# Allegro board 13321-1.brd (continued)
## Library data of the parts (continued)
PC4715 PC4716 PC4724-PC4728 PC4734 PC4736 PC4737 PC4743 = C805H58: tolerance: 78.22610.51L
PC4805 PC4810-PC4813 PC4901 PC4903-PC4905 = C805H58: tolerance: 78.22610.L2L
PC4806 = C603H36: tolerance: 78.10422.L0L
PC4907 = C402H22: tolerance: 78.10324.L0L
PD4201 = D5436AKH98: tolerance: 83.22R03.03G
PD4204 = SOT-23-10H44: tolerance: 83.0024V.0A1
PD4302 = SOD123FLAKH40: tolerance: 83.SMF18.0AH
PD4401 PD4405 PD4406 = SOD323AKH40: tolerance: 83.1R504.B8F
PD4402 = SMPC4665-3P-UH48: tolerance: 83.8R010.A87
PD4403 = SOD323AKH42: tolerance: 83.04148.D1H
PG4401-PG4408 PG4532 PG4535 PG4707 PG4708 PG4801 = GAP-CLOSE-PWR-3: tolerance: ZZ.CLOSE.001
PG4901-PG4909 PG4917 PG4918 PG5101 = GAP-CLOSE-PWR: tolerance: ZZ.CON2d.XXX
PL4401 = L11510030H158: tolerance: 68.2R210.20C
PL4501 = L736630H119: tolerance: 68.3R310.20A
PL4503 = L7066-1830-UH119: tolerance: 68.4R71A.20H
PL4701 = L109100-2430-UH158: tolerance: 068.R2210.2011
PL4801 PL4901 = L4947-1015H119: tolerance: 68.R6810.20E
PQ4201 Q1201 = SOT23DGS2D4H44: tolerance: 84.00301.A31
PQ4202 Q2603 Q5401 = SOT23CBE2D6H46: tolerance: 84.03904.P11
PQ4401 PQ4406 Q1202 Q1901 Q2401 Q2403 Q2505 Q2602 Q2901 Q5403 Q5404 Q6205 = SOT23DGS2D4H44: tolerance: 84.2N702.J31
PQ4405 PQ4407 PQ4411 PQ4413 Q1701 Q1801 Q2601 Q3601 Q5402 Q6204 Q6701 U2901 = SOT-363H44: tolerance: 84.2N702.A3F
PQ4408 Q2404 = SOT23CBE2D4H44: tolerance: 84.T3906.A11
PR4202 PR4527 R3024 = R402H16: tolerance: 64.15025.6DL
PR4203 PR4909 R405 R706 R710 R1701 R1717 R1724 R1726 R1902 R1905 R2001 R2004 R2017 R2021-R2025 R2414 R2415 R2418 R2436 R2439 R2443 R2446 R2448 R2451 R2452 R2454 R2916 R2919 R2920 R5412 R5420 R6203 R6609-R6620 R6623 R6626 = R402H16: tolerance: 63.10334.1DL
PR4204 = R402H16: tolerance: 63.22234.1DL
PR4205 PR4206 R5205 = R402H16: tolerance: 63.33034.1DL
PR4207 = R603H22: tolerance: 63.24434.15L
PR4208 = R603H22: tolerance: 63.47333.15L
PR4209 PR4410 PR4412 PR4416 PR4429 PR4435 PR4437 PR4449 PR4470 PR4471 PR4534 R1715 R1727 R2007 R2013 R2412 R2413 R2421 R2442 R2445 R2447 R2450 R2455 R2711 R2722 R2905 R2918 R3503 R3607 R5413 R6208 R6401 R6602 R6701 = R402H16: tolerance: 63.10434.1DL
PR4401 = R402H16: tolerance: 64.18235.6DL
PR4402 PR4420 PR4607 PR4806 = R402H16: tolerance: 64.75025.6DL
PR4403 = R805H24: tolerance: 63.10031.16L
PR4404 PR4440 = R402H16: tolerance: 63.12434.1DL
PR4405 PR4424 PR4431 PR4441 PR4453 PR4460 PR4461 R707 R713 R1725 R2406 R2407 = R402H16: tolerance: 64.10035.6DL
PR4406 PR4417 PR4430 PR4434 PR4438 PR4455 PR4458 PR4462 PR4466 PR4467 PR4469 PR4504 PR4506 PR4515 PR4532 PR4615 PR4625 PR4702 PR4802 PR4804 PR4807 PR4902 PR4905-PR4907 PR4914 PR5101 R404 R1201 R1202 R1205 R1501 R1706 R1707 R1709 R1710 R1713 R1718 R1729 R1810 R1904 R2002 R2008-R2010 R2015 R2016 R2019 R2020 R2028 R2101 R2103 R2105 R2112 R2117 R2118 R2401 R2416 R2417 R2426-R2428 R2430 R2435 R2437 R2440 R2441 R2444 R2453 R2457 R2601 R2611 R2612 R2701 R2705 R2708 R2714 R3413-R3416 R3501 R3504 R3505 R3507 R3609-R3611 R3802 R4301 R5201 R5202 R5421 R5422 R5601 R6202 R6216 R6622 R6625 R6628 R6629 = 0R0402-PAD-1: tolerance: ZZ.00PAD.M11
PR4407 = R402H16: tolerance: 64.6R805.6DL
PR4408 = R603H22: tolerance: 64.20R05.55L
PR4409 = R402H16: tolerance: 64.10015.6DL
PR4411 R709 R712 = R402H16: tolerance: 64.47025.6DL
PR4413 PR4415 PR4419 PR4421 PR4448 PR4452 PR4456 PR4457 PR4463 PR4464 PR4501 PR4525 PR4530 PR4535 PR4626 PR4917 PR4918 PR4925 PR4926 R1704 R1705 R1708 R1728 R2005 R2026 R2027 R2123 R2424 R2434 R2438 R2602 R2710 R2712 R2716 R2923 R3704 R3710 R5224 R5418 R6212 R6213 R6603 R6608 R6621 R6624 R6627 R6705-R6709 = R402H16: tolerance: 63.R0034.1DL
PR4414 PR4432 = R402H16: tolerance: 63.33234.1DL
PR4418 = R1206H28: tolerance: 63.33232.11L
PR4422 = R402H16: tolerance: 63.18534.L0L
PR4423 PR4450 PR4523 PR4619 R2405 = R402H16: tolerance: 64.10025.6DL
PR4425 PR4801 R2917 R5423 R6205 R6211 = R603H22: tolerance: 63.00000.00L
PR4426 = R3720H40: tolerance: 64.R0105.7FL
PR4427 PR4529 PR4533 PR4701 = R805H24: tolerance: 64.2R205.16L
PR4428 PR4468 PR4601 PR4903 R5411 = R402H16: tolerance: 64.15035.6DL
PR4433 R1802 R1901 = R402H16: tolerance: 63.10534.1DL
PR4436 = R402H16: tolerance: 64.22035.6DL
PR4439 = R402H16: tolerance: 64.40215.6DL
PR4442 = R402H16: tolerance: 64.41235.6DL
PR4443 = R2512H32: tolerance: 64.R0105.97L
PR4444 = R402H16: tolerance: 64.28735.6DL
PR4445 = R402H16: tolerance: 64.33025.6DL
PR4446 R2433 R2707 R3506 R6204 = R402H16: tolerance: 64.20025.6DL
PR4447 = R402H16: tolerance: 64.18035.6DL
PR4451 = R402H16: tolerance: 64.68035.6DL
PR4454 R2609 R2908 R2910 = R402H14: tolerance: 64.10R05.6DL
PR4465 = R402H16: tolerance: 64.31635.6DL
PR4502 = R402H16: tolerance: 63.20134.1DL
PR4512 = R402H16: tolerance: 64.66515.6DL
PR4517 = R402H16: tolerance: 64.34825.6DL
PR4524 PR4528 = R603H22: tolerance: 63.1R534.15L
PR4526 = R402H16: tolerance: 64.97615.6DL
PR4531 = R402H16: tolerance: 64.49925.6DL
PR4602 = NTC-402H22-U: tolerance: 69.60037.031
PR4603 PR4611 R703 = R402H16: tolerance: 64.75R05.6DL
PR4604 = R402H16: tolerance: 64.49935.6DL
PR4605 = R402H16: tolerance: 64.71525.6DL
PR4608 PR4612 = R402H16: tolerance: 64.39025.6DL
PR4609 = R402H16: tolerance: 64.56025.6DL
PR4610 = R402H16: tolerance: 64.39235.6DL
PR4613 PR4618 PR4624 = R603H22: tolerance: 63.10033.15L
PR4614 R2607 = R402H16: tolerance: 64.20015.6DL
PR4616 PR4617 R1801 R1807-R1809 R1811 R1812 R1908 R2718 R2719 R5401-R5408 R6601 R6604 = 0R0402-PAD-1: tolerance: ZZ.00PAD.M11; signal model: R402H16_0R2J-2-GP
PR4620 = R402H16: tolerance: 64.34015.6DL
PR4621 PR4623 R704 = R402H16: tolerance: 64.13005.6DL
PR4622 = R402H16: tolerance: 64.54R95.6DL
PR4627 = R402H16: tolerance: 64.47515.6DL
PR4703 PR4901 = R603H24: tolerance: 64.2R205.L0L
PR4704 = R402H16: tolerance: 64.23215.6DL
PR4705 = R402H16: tolerance: 64.16225.6DL
PR4706 = R402H16: tolerance: 64.29415.6DL
PR4707 = NTC-402H22-U: tolerance: 69.60037.011
PR4803 = R402H16: tolerance: 63.10534.L1L
PR4805 = R402H16: tolerance: 64.10035.L3L
PR4904 = R402H16: tolerance: 64.12035.6DL
PR4910 R604 R605 R1702 R1703 R1909 R1919 R2006 R2011 R2012 R2014 R2018 R2432 R2449 R2717 R2921 R2922 R3601 R3603 R6201 = R402H16: tolerance: 63.10234.1DL
PT4501 PT4502 = CT3528H79: tolerance: 77.C2271.45L
PT4702 = CT7343H119: tolerance: 77.23361.061
PU4201 PU4403 PU4405 = PPAK-8P-2H45: tolerance: 84.07121.037
PU4401 = QFN28-G2D7H32: tolerance: 074.24770.0003
PU4402 = TSOIC8H48: tolerance: 74.00393.C2G
PU4404 = SC70-6H44: tolerance: 74.00199.07P
PU4406 = PPAK-8P-G5324H44-COLAY: tolerance: ZZ.00215.037
PU4501 PU4502 = SON5Z3025H18: tolerance: 84.87381.03G
PU4503 = QFN20-G1D75H32: tolerance: 74.51225.073
PU4601 = QFN32J4-G2D9-U1H40: tolerance: 74.51624.073
PU4701 = DFN8J4535-G4122-U1H40: tolerance: 74.97374.043
PU4801 = QFN10M3-G4P-UH34: tolerance: 74.08208.K73
PU4901 = QFN10M3-G4P-UH34: tolerance: 74.08206.C73
PU4902 = MSOP10-G2D5H44: tolerance: 74.05338.079
PU5101 = SOT-23-5H58: tolerance: 74.70215.03F
Q2402 Q6203 = SOT23DGS2D4H48: tolerance: 84.02130.031
Q6201 = SOT23CBE2D4H44: tolerance: 84.00144.N11
Q6202 = SOT23DGS2D8H56: tolerance: 84.P8503.031
R401 = R402H16: tolerance: 63.62034.1DL
R402 R406 R1916-R1918 R1920 = R402H16: tolerance: 63.51034.1DL
R403 = R402H16: tolerance: 63.56034.1DL
R407 = R402H16: tolerance: 64.20005.6DL
R408 = R402H16: tolerance: 64.12105.6DL
R409 R702 R901 = R402H14: tolerance: 64.10005.6DL
R410 = R402H16: tolerance: 63.47134.1DL
R601 R602 R606 R2003 = R402H16: tolerance: 64.49R95.6DL
R603 R1714 = R402H16: tolerance: 64.82015.6DL
R701 R2429 = R402H16: tolerance: 63.43034.1DL
R705 R5414-R5417 = R402H16: tolerance: 63.15134.1DL
R801 R3707 R3711 = R402H16: tolerance: 64.24R95.6DL
R1204 = R402H16: tolerance: 63.20534.1DL
R1206 R1207 = R402H16: tolerance: 64.66R55.6DL
R1208 = R402H16: tolerance: 63.22434.1DL
R1601 R1803 R1906 = R402H16: tolerance: 64.30015.6DL
R1602 = R402H16: tolerance: 64.22R65.6DL
R1720 R1721 R1903 R1913 R2425 R2431 = R402H16: tolerance: 63.33434.1DL
R1804 R2720 = R402H16: tolerance: 63.R0034.1DL; signal model: R402H16_0R2J-2-GP
R1805 R1806 R1907 R1912 R2419 R2420 R2422 R2423 = R402H16: tolerance: 63.33034.1DL; signal model: R402H16_33R2J-2-GP
R1911 = R402H16: tolerance: 63.33034.1DL; signal model: R402H16_0R2J-2-GP
R1915 R2504 = R402H16: tolerance: 63.10634.1DL
R2110 = R402H16: tolerance: 64.5R105.6DL
R2114 R3801 = R805H24: tolerance: 63.R0031.16L
R2403 = R603H22: tolerance: 64.2R205.55L
R2404 = R402H16: tolerance: 64.64925.6DL
R2408 R2409 R5419 = 0R0402-PAD: tolerance: ZZ.R0402.001
R2501 R2912 R2913 = R402H16: tolerance: 63.47234.1DL
R2603 R2604 = R402H16: tolerance: 64.75015.6DL
R2608 = R402H16: tolerance: 64.24325.6DL
R2610 = NTC-603H38: tolerance: 69.60035.041
R2709 R3602 R5410 = R402H16: tolerance: 64.20035.6DL
R2914 R5233 R6702 = R603H22: tolerance: 63.R0033.15L
R2915 = R402H16: tolerance: 63.47434.1DL
R3508 = R402H16: tolerance: 64.22125.6DL
R3701 R3703 R3706 R3709 = R402H16: tolerance: 64.18015.6DL
R3702 R3708 = R402H16: tolerance: 64.2R005.6DL
R5203 R5204 = R402H14: tolerance: 63.10134.1DL
R6210 = R603H22: tolerance: 63.10133.15L
R6605 = R402H16: tolerance: 64.15015.6DL
R6606 = R402H16: tolerance: 63.20334.1DL
RN401 = ARES8-CN24H22: tolerance: 66.51036.A8L
RN1501 RN1811 RN2008 RN2602 RN2901 RN5401 RN6204 RN6601 = ARES2H16: tolerance: 66.22236.04L
RN1505 RN1506 RN1601 RN1809 RN1902 RN2002 RN2011 RN2012 = ARES8-CN24-MUH20: tolerance: 66.10336.08L
RN1701 RN1703 RN1801 RN1803 RN1804 RN1810 RN2006 RN2007 RN6201 = ARES2H18: tolerance: 66.10336.04L
RN1702 = SMD-ARES4H20: tolerance: 66.R0036.04L
RN1802 = SMD-ARES4H18: tolerance: 66.10236.04L
RN1806 = ARES8-CN24H22: tolerance: 66.R0036.A8L; signal model: ARES8-CN24H22_SRN0J-7-GP-U
RN1807 = ARES8-CN24-UH20: tolerance: 66.22236.A8L
RN1901 = SMD-ARES4H20: tolerance: 66.20336.04L
RN2401 = SMD-ARES4H18: tolerance: 66.47236.04L
RN2601 RN2701 RN6604 = 0R4P2R-PAD: tolerance: ZZ.0R04P.ZZZ
RN4301 RN5201 = ARES8-CN24H20: tolerance: 66.10136.A8L
RN5203 = ARES8-CN24H20: tolerance: 66.10436.A8L
RN5402 RN5403 = ARES8-CN24H20: tolerance: 66.47136.08L
RN6202 = SMD-ARES4H18: tolerance: 66.33036.04L
SPI25 = SOIC8-1H86: tolerance: 72.25647.00A
SPR1 SPR2 = SPR7732H229: tolerance: 34.4T025.001
TC1201 = CT7343H79: tolerance: 79.33719.20L
THM261 = MSOP8-1H44: tolerance: 74.07718.0B9
TP1 = 50505-0084N-002: tolerance: 20.K0667.008
TP402 TP501 TP601-TP608 TP619 TP620 TP701-TP705 TP801 TP1501 TP1502 TP1702-TP1707 TP1801-TP1803 TP1901 TP1902 TP2002-TP2009 TP2014 TP2015 TP2019 TP2101-TP2109 TP2201-TP2208 TP2408 TP2409 TP2702 TP6601-TP6604 TP9601 TP9602 TP9611-TP9624 TP9626-TP9653 = TPAD14-OP: tolerance: ZZ.PAD14.001
TR3401 = L125100-4PH24: tolerance: 69.10118.001; signal model: FILTER2012-4PH48_FILTER-4P-62-GP
TR3402 TR5208 = L125100-4PH24: tolerance: 69.10118.001
TR3404 TR3405 = L125100-4PH24: tolerance: 69.10118.001; signal model: L125100-4PH30_FILTER-4P-70-GP
U701 = SC70-5H44: tolerance: 73.01G07.0HG
U2101 = DFN9J2015H32: tolerance: 74.59147.093
U3502 = SOT-23-5H56: tolerance: 074.06288.009B
U3503 = QFN16-G1D8-UH32: tolerance: 74.02544.073; signal model: QFN16-G1D8-UH32_TPS2544RTER-GP
U3601 = SON14J3020-G2610H34: tolerance: 74.22966.093
U3801 = MSOP8-1H44: tolerance: 74.06288.079
U5201 = SOT-23-5H51: tolerance: 74.09724.09F
U5602 = DFN10G2510H26: tolerance: 75.01045.073
U6601 = QFN48G7-G5D7H26: tolerance: 071.32151.000U
U6602 U6701 = LGA16-3030-H40: tolerance: 74.LNG3D.0BZ
USB1 = SKT-USB14-160155-U: tolerance: 022.10005.0441
USB2 = SKT-USB13-158172-1: tolerance: 22.10341.A81
X1801 = OSC-3225-4P-3H36: tolerance: 82.30004.891
X1901 = SMD-OSC2H56: tolerance: 82.30001.A41
X6601 = OSC-3225-4P-4H36: tolerance: 82.30006.641

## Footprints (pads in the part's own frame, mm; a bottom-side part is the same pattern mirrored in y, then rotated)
0R4P2R-PAD
  custom 0.089x0.089 smd: 1(-0.325,-0.599) 2(0.325,-0.599) 3(0.325,0.599) 4(-0.325,0.599)
0R0402-PAD
  custom 0.14x0.14 smd: 1(0,0.445) 2(0,-0.445)
0R0402-PAD-1
  custom 0.14x0.14 smd: 1(0,0.445) 2(0,-0.445)
0R0603-PAD-1-U
  custom 0.254x0.254 smd: 1(0,0.66) 2(0,-0.66)
0R0805-PAD-1-U
  rect 1.549x1.333 smd: 1(0,0.838) 2(0,-0.838)
2SJ3095-013111F
  oval 1.321x2.235 hole 0.61x1.524: 1(-4.85,8.4) 2(4.7,2.9) 3(-4.85,0.6) 4(4.7,0) 5(4.7,8.4) 6(4.7,5.65) MS(-4.85,4.3)
50224-0040N-001
  rect 0.61x1.549 smd: 1(-1.5,3.875) 2(-0.5,3.875) 3(0.5,3.875) 4(1.5,3.875)
  rect 1.194x1.803 smd: 5(-2.797,0) 6(2.797,0)
50224-0080N-W02
  rect 0.406x1.549 smd: 1(-3.5,3.875) 2(-2.5,3.875) 3(-1.5,3.875) 4(-0.5,3.875) 5(0.5,3.875) 6(1.5,3.875) 7(2.5,3.875) 8(3.5,3.875)
  rect 1.194x1.803 smd: 9(-4.797,0) 10(4.797,0)
50503-0040N-W01
  rect 0.406x1.295 smd: 1(-1.5,2.8) 2(-0.5,2.8) 3(0.5,2.8) 4(1.5,2.8)
  rect 1.803x1.397 smd: 5(-3.65,0) 6(3.65,0)
50505-0084N-002
  rect 0.406x1.295 smd: 1(3.5,3.25) 2(2.5,3.25) 3(1.5,3.25) 4(0.5,3.25) 5(-0.5,3.25) 6(-1.5,3.25) 7(-2.5,3.25) 8(-3.5,3.25)
  rect 0.991x2.007 smd: 9(6.1,0) 10(-6.1,0)
50588-02601-001-U
  rect 0.406x1.092 smd: 1(12.5,2.15) 2(11.5,2.15) 3(10.5,2.15) 4(9.5,2.15) 5(8.5,2.15) 6(7.5,2.15) 7(6.5,2.15) 8(5.5,2.15) 9(4.5,2.15) 10(3.5,2.15) 11(2.5,2.15) 12(1.5,2.15) 13(0.5,2.15) 14(-0.5,2.15) 15(-1.5,2.15) 16(-2.5,2.15) 17(-3.5,2.15) 18(-4.5,2.15) 19(-5.5,2.15) 20(-6.5,2.15) 21(-7.5,2.15) 22(-8.5,2.15) 23(-9.5,2.15) 24(-10.5,2.15) 25(-11.5,2.15) 26(-12.5,2.15)
  rect 2.21x3.2 smd: 27(14.995,0) 28(-14.995,0)
87212-1002N
  rect 0.61x1.549 smd: 1(-4.5,-2.525) 2(-3.5,-2.525) 3(-2.5,-2.525) 4(-1.5,-2.525) 5(-0.5,-2.525) 6(0.5,-2.525) 7(1.5,-2.525) 8(2.5,-2.525) 9(3.5,-2.525) 10(4.5,-2.525)
  rect 1.194x1.803 smd: 11(-5.797,0) 12(5.797,0)
AFTE14P-75
  round 0.356 smd: 1(0,0)
ARES2H16
  rect 0.356x0.66 smd: 1(-0.325,-0.599) 2(0.325,-0.599) 3(0.325,0.599) 4(-0.325,0.599)
ARES2H18
  rect 0.356x0.66 smd: 1(-0.325,-0.599) 2(0.325,-0.599) 3(0.325,0.599) 4(-0.325,0.599)
ARES8-CN24-MUH20
  rect 0.61x0.66 smd: 1(-0.9,-0.486) 4(0.9,-0.486) 5(0.9,0.486) 8(-0.9,0.486)
  rect 0.305x0.66 smd: 2(-0.25,-0.486) 3(0.25,-0.486) 6(0.25,0.486) 7(-0.25,0.486)
ARES8-CN24-UH20
  rect 0.61x0.66 smd: 1(-0.9,-0.486) 4(0.9,-0.486) 5(0.9,0.486) 8(-0.9,0.486)
  rect 0.305x0.66 smd: 2(-0.25,-0.486) 3(0.25,-0.486) 6(0.25,0.486) 7(-0.25,0.486)
ARES8-CN24H20
  rect 0.61x0.66 smd: 1(-0.9,-0.486) 4(0.9,-0.486) 5(0.9,0.486) 8(-0.9,0.486)
  rect 0.305x0.66 smd: 2(-0.25,-0.486) 3(0.25,-0.486) 6(0.25,0.486) 7(-0.25,0.486)
ARES8-CN24H22
  rect 0.61x0.66 smd: 1(-0.9,-0.486) 4(0.9,-0.486) 5(0.9,0.486) 8(-0.9,0.486)
  rect 0.305x0.66 smd: 2(-0.25,-0.486) 3(0.25,-0.486) 6(0.25,0.486) 7(-0.25,0.486)
AYF531635
  rect 0.305x0.813 smd: 1(3.75,2.5) 2(3.25,2.5) 3(2.75,2.5) 4(2.25,2.5) 5(1.75,2.5) 6(1.25,2.5) 7(0.75,2.5) 8(0.25,2.5) 9(-0.25,2.5) 10(-0.75,2.5) 11(-1.25,2.5) 12(-1.75,2.5) 13(-2.25,2.5) 14(-2.75,2.5) 15(-3.25,2.5) 16(-3.75,2.5)
  rect 0.406x0.813 smd: 17(4.75,0) 18(-4.75,0)
BGA1168M4024H64
  round 0.508 smd: A3(18.177,-11.314) A62(-18.722,-11.314) AW1(19.314,10.727) AW63(-19.314,10.743) AY2(18.771,11.314) AY62(-18.748,11.314) B2(18.806,-10.806) B63(-19.314,-10.722) C1(19.314,-10.177)
  custom 0.089x0.089 smd: A4(17.421,-11.314) A5(16.76,-11.314) A6(15.564,-11.314) A59(-16.586,-11.314) A60(-17.412,-11.314) A61(-18.072,-11.314) AT1(19.314,8.683) AT63(-19.314,8.533) AU1(19.314,9.343) AU63(-19.314,9.359) AV1(19.314,10.004) AV2(18.654,9.993) AV62(-18.664,10.004) AV63(-19.314,10.019) AW3(17.993,10.654) AY3(18.047,11.314) AY4(17.387,11.314) AY5(16.726,11.314) AY59(-16.774,11.314) AY60(-17.434,11.314) AY61(-18.095,11.314) B61(-18.001,-10.654) C62(-18.664,-9.93) C63(-19.314,-9.998) D1(19.314,-9.453) D63(-19.314,-9.338) E1(19.314,-8.792) E63(-19.314,-8.667) F1(19.314,-7.878)
  custom 0.07x0.07 smd: A8(14.776,-11.314) A11(12.948,-11.314) A12(12.198,-11.314) A14(11.284,-11.314) A17(9.62,-11.314) A18(8.706,-11.314) A23(6.128,-11.314) A24(5.291,-10.989) A25(4.6,-11.314) A27(3.474,-11.314) A28(2.783,-10.989) A29(2.093,-11.314) A31(0.966,-11.314) A32(0.276,-10.989) A33(-0.415,-11.314) A35(-1.541,-11.314) A36(-2.232,-10.989) A37(-2.922,-11.314) A39(-4.049,-11.314) A40(-4.739,-10.989) A41(-5.43,-11.314) A43(-6.556,-11.314) A44(-7.247,-10.989) A45(-7.937,-11.314) A47(-9.064,-11.314) A48(-9.754,-10.989) A49(-10.444,-11.314) A51(-11.571,-11.314) A52(-12.262,-10.989) A53(-12.952,-11.314) A55(-14.079,-11.314) A56(-14.769,-10.989) A57(-15.459,-11.314) AA1(19.314,0.402) AA2(18.664,0.402) AA3(18.014,0.364) AA61(-18.014,0.324) AA62(-18.664,0.362) AA63(-19.314,0.362) AC1(19.314,1.152) AC2(18.664,1.152) AC3(18.014,1.19) AC61(-18.014,1.15) AC62(-18.664,1.112) AC63(-19.314,1.112) AD1(19.314,1.901) AD2(18.664,1.901) AD3(18.014,1.863) AD61(-18.014,1.823) AD62(-18.664,1.861) AD63(-19.314,1.861) AE61(-18.014,2.648) AE62(-18.664,2.61) AE63(-19.314,2.61) AF1(19.314,2.65) AF2(18.664,2.65) AF3(18.014,2.688) AG1(19.314,3.4) AG2(18.664,3.4) AG3(18.014,3.361) AG62(-18.339,3.288) AG63(-18.989,3.288) AH1(19.314,4.149) AH2(18.664,4.149) AH3(18.014,4.187) AH61(-18.014,3.964) AH62(-18.664,3.964) AH63(-19.314,3.964) AJ62(-18.339,4.64) AJ63(-18.989,4.64) AK1(19.314,4.898) AK2(18.664,4.898) AK3(18.014,4.86) AK61(-18.014,5.209) AK62(-18.664,5.315) AL1(19.314,5.647) AL2(18.664,5.647) AL3(18.014,5.686) AM1(19.314,6.397) AM2(18.664,6.397) AM3(18.014,6.359) AM61(-18.014,6.501) AM62(-18.664,6.395) AN1(19.314,7.146) AN2(18.664,7.146) AN3(18.014,7.184) AN62(-18.339,7.07) AN63(-18.989,7.07) AP1(19.314,7.895) AP2(18.664,7.895) AP3(18.014,7.857) AP61(-18.014,7.746) AP62(-18.664,7.746) AP63(-19.314,7.746) AV6(15.977,10.014) AV7(15.151,10.014) AV8(14.478,10.014) AV10(13.653,10.014) AV11(12.98,10.014) AV12(12.154,10.014) AV14(11.481,10.014) AV15(10.656,10.014) AV17(9.454,10.014) AV19(8.21,10.014) AV21(6.917,10.014) AV23(5.672,10.014) AV25(4.321,10.014) AV27(3.076,10.014) AV29(1.783,10.014) AV31(0.539,10.014) AV34(-0.71,10.014) AV35(-1.535,10.014) AV36(-2.284,10.014) AV37(-3.11,10.014) AV39(-3.859,10.014) AV40(-4.685,10.014) AV41(-5.434,10.014) AV42(-6.26,10.014) AV43(-7.009,10.014) AV44(-7.834,10.014) AV46(-8.584,10.014) AV47(-9.409,10.014) AV49(-10.158,10.014) AV50(-10.984,10.014) AV52(-12.342,10.014) AV54(-13.586,10.014) AV56(-14.879,10.014) AV58(-16.124,10.014) AW5(16.688,10.664) AW6(15.939,10.664) AW7(15.189,10.664) AW8(14.44,10.664) AW10(13.691,10.664) AW11(12.942,10.664) AW12(12.192,10.664) AW14(11.443,10.664) AW15(10.694,10.664) AW16(10.092,10.339) AW17(9.454,10.664) AW18(8.778,10.339) AW19(8.103,10.664) AW21(7.023,10.664) AW22(6.348,10.339) AW23(5.672,10.664) AW24(4.996,10.339) AW25(4.321,10.664) AW26(3.645,10.339) AW27(2.97,10.664) AW29(1.89,10.664) AW30(1.214,10.339) AW31(0.539,10.664) AW33(-0.137,10.339) AW34(-0.71,10.664) AW35(-1.535,10.664) AW36(-2.284,10.664) AW37(-3.11,10.664) AW39(-3.859,10.664) AW40(-4.685,10.664) AW41(-5.434,10.664) AW42(-6.26,10.664) AW43(-7.009,10.664) AW44(-7.834,10.664) AW46(-8.584,10.664) AW47(-9.409,10.664) AW49(-10.158,10.664) AW50(-10.984,10.664) AW51(-11.666,10.339) AW52(-12.342,10.664) AW53(-13.017,10.339) AW54(-13.693,10.664) AW56(-14.772,10.664) AW57(-15.448,10.339) AW58(-16.124,10.664) AY6(15.939,11.314) AY7(15.189,11.314) AY8(14.44,11.314) AY10(13.691,11.314) AY11(12.942,11.314) AY12(12.192,11.314) AY14(11.443,11.314) AY15(10.694,11.314) AY16(10.13,10.989) AY17(9.454,11.314) AY18(8.778,10.989) AY22(6.348,10.989) AY23(5.672,11.314) AY24(4.996,10.989) AY25(4.321,11.314) AY26(3.645,10.989) AY30(1.214,10.989) AY31(0.539,11.314) AY33(-0.137,10.989) AY34(-0.71,11.314) AY35(-1.535,11.314) AY36(-2.284,11.314) AY37(-3.11,11.314) AY39(-3.859,11.314) AY40(-4.685,11.314) AY41(-5.434,11.314) AY42(-6.26,11.314) AY43(-7.009,11.314) AY44(-7.834,11.314) AY46(-8.584,11.314) AY47(-9.409,11.314) AY49(-10.158,11.314) AY50(-10.984,11.314) AY51(-11.666,10.989) AY52(-12.342,11.314) AY53(-13.017,10.989) AY57(-15.448,10.989) AY58(-16.124,11.314) B6(15.196,-10.672) B8(14.423,-10.672) B9(13.598,-10.672) B11(12.617,-10.672) B12(11.845,-10.672) B14(11.02,-10.672) B15(10.039,-10.672) B17(9.267,-10.672) B18(8.442,-10.672) B21(7.042,-10.118) B22(6.689,-10.672) B23(5.864,-10.672) B24(5.291,-10.339) B25(4.6,-10.664) B26(4.037,-10.339) B27(3.474,-10.664) B28(2.783,-10.339) B29(2.093,-10.664) B30(1.53,-10.339) B31(0.966,-10.664) B32(0.276,-10.339) B33(-0.415,-10.664) B34(-0.978,-10.339) B35(-1.541,-10.664) B36(-2.232,-10.339) B37(-2.922,-10.664) B38(-3.485,-10.339) B39(-4.049,-10.664) B40(-4.739,-10.339) B41(-5.43,-10.664) B42(-5.993,-10.339) B43(-6.556,-10.664) B44(-7.247,-10.339) B45(-7.937,-10.664) B46(-8.5,-10.339) B47(-9.064,-10.664) B48(-9.754,-10.339) B49(-10.444,-10.664) B50(-11.008,-10.339) B51(-11.571,-10.664) B52(-12.262,-10.339) B53(-12.952,-10.664) B54(-13.515,-10.339) B55(-14.079,-10.664) B56(-14.769,-10.339) B57(-15.459,-10.664) C8(14.776,-10.118) C9(13.964,-10.118) C11(12.96,-10.118) C12(12.198,-10.118) C14(11.386,-10.118) C15(10.382,-10.118) C17(9.62,-10.118) C18(8.807,-10.118) C23(6.229,-10.118) F61(-18.014,-7.842) F62(-18.664,-7.88) F63(-19.314,-7.88) G1(19.314,-7.091) G2(18.664,-7.091) G3(18.014,-7.129) H61(-18.014,-7.169) H62(-18.664,-7.131) H63(-19.314,-7.131) J1(19.314,-6.341) J2(18.664,-6.341) J3(18.014,-6.303) J61(-18.014,-6.343) J62(-18.664,-6.381) J63(-19.314,-6.381) K1(19.314,-5.592) K2(18.664,-5.592) K3(18.014,-5.63) K61(-18.014,-5.67) K62(-18.664,-5.632) K63(-19.314,-5.632) L1(19.314,-4.843) L2(18.664,-4.843) L3(18.014,-4.805) L61(-18.014,-4.845) L62(-18.664,-4.883) L63(-19.314,-4.883) N1(19.314,-4.093) N2(18.664,-4.093) N3(18.014,-4.132) N61(-18.014,-4.172) N62(-18.664,-4.134) N63(-19.314,-4.134) P1(19.314,-3.344) P2(18.664,-3.344) P3(18.014,-3.306) P61(-18.014,-3.346) P62(-18.664,-3.384) P63(-19.314,-3.384) T1(19.314,-2.595) T2(18.664,-2.595) T3(18.014,-2.633) T61(-18.014,-2.673) T62(-18.664,-2.635) T63(-19.314,-2.635) U1(19.314,-1.846) U2(18.664,-1.846) U3(18.014,-1.807) U61(-18.014,-1.848) U62(-18.664,-1.886) U63(-19.314,-1.886) V1(19.314,-1.096) V2(18.664,-1.096) V3(18.014,-1.134) V61(-18.014,-1.174) V62(-18.664,-1.136) V63(-19.314,-1.136) Y1(19.314,-0.347) Y2(18.664,-0.347) Y3(18.014,-0.309) Y61(-18.014,-0.349) Y62(-18.664,-0.387) Y63(-19.314,-0.387)
  custom 0.064x0.064 smd: A9(13.862,-11.314) A15(10.37,-11.314) A21(7.042,-11.314) AK63(-19.314,5.315) AM63(-19.314,6.395) AY19(8.103,11.314) AY21(7.023,11.314) AY27(2.97,11.314) AY29(1.89,11.314) AY54(-13.693,11.314) AY56(-14.772,11.314)
  round 0.305 smd: A20(7.791,-11.314) AA4(17.363,0.364) AA59(-16.713,0.324) AA60(-17.363,0.324) AB5(16.678,0.738) AB6(16.027,0.738) AB7(15.377,0.738) AB8(14.727,0.738) AC4(17.363,1.19) AC59(-16.713,1.15) AC60(-17.363,1.15) AD4(17.363,1.863) AD5(16.678,1.691) AD6(16.027,1.691) AD7(15.377,1.691) AD8(14.727,1.691) AD59(-16.713,1.823) AD60(-17.363,1.823) AE5(16.678,2.643) AE6(16.027,2.643) AE7(15.377,2.643) AE8(14.727,2.643) AE59(-16.713,2.648) AE60(-17.363,2.648) AF4(17.363,2.688) AG4(17.363,3.361) AG5(16.678,3.596) AG6(16.027,3.596) AG7(15.377,3.596) AG8(14.727,3.596) AG21(7.359,3.807) AG60(-17.038,3.288) AG61(-17.689,3.288) AH4(17.363,4.187) AH10(13.662,4.162) AH11(12.849,4.162) AH13(12.036,4.162) AH14(11.223,4.162) AH16(10.41,4.162) AH17(9.598,4.162) AH19(8.785,4.162) AH20(7.972,4.162) AH60(-17.363,3.964) AJ5(16.678,4.548) AJ6(16.027,4.548) AJ7(15.377,4.548) AJ8(14.727,4.548) AJ10(13.662,4.812) AJ11(12.849,4.812) AJ13(12.036,4.812) AJ14(11.223,4.812) AJ60(-17.038,4.64) AJ61(-17.689,4.64) AK4(17.363,4.86) AK8(15.011,5.137) AK18(9.466,4.952) AK20(8.513,4.952) AK21(7.561,4.952) AK60(-17.363,5.209) AL4(17.363,5.686) AL5(16.413,5.462) AL7(15.575,5.462) AL8(15.011,5.787) AL10(13.657,5.462) AL11(13.093,5.787) AL13(11.738,5.462) AL15(11.174,5.787) AL17(10.092,5.268) AL18(9.466,5.602) AL20(8.513,5.602) AL21(7.561,5.602) AL22(6.608,5.602) AL23(5.786,5.602) AL25(4.81,5.602) AL26(3.858,5.602) AL28(2.905,5.602) AL29(1.953,5.602) AL31(1.054,5.277) AL32(0.49,5.602) AL33(-0.412,5.602) AL35(-1.415,5.602) AL36(-2.266,5.602) AL38(-3.32,5.602) AL39(-4.228,5.277) AL40(-4.817,5.602) AL42(-5.63,5.602) AL43(-6.582,5.602) AL45(-7.56,5.602) AL46(-8.487,5.602) AL48(-9.542,5.602) AL49(-10.443,5.602) AL51(-11.447,5.602) AL52(-12.269,5.602) AL54(-13.295,5.602) AL55(-14.248,5.602) AL57(-15.195,5.602) AL58(-16.094,5.602) AL60(-17.038,5.855) AL61(-17.689,5.855) AM4(17.363,6.359) AM5(16.413,6.112) AM7(15.575,6.112) AM8(15.011,6.437) AM10(13.657,6.112) AM11(13.093,6.437) AM13(11.738,6.112) AM15(11.174,6.437) AM17(10.092,5.919) AM18(9.466,6.252) AM20(8.513,6.252) AM21(7.561,6.252) AM22(6.608,6.252) AM23(5.786,6.252) AM25(4.81,6.252) AM26(3.858,6.252) AM28(2.905,6.252) AM29(1.953,6.252) AM31(1.054,5.927) AM32(0.49,6.252) AM33(-0.412,6.252) AM35(-1.415,6.252) AM36(-2.266,6.252) AM38(-3.32,6.252) AM40(-4.817,6.252) AM42(-5.63,6.252) AM43(-6.582,6.252) AM45(-7.56,6.252) AM46(-8.487,6.252) AM48(-9.542,6.252) AM49(-10.443,6.252) AM51(-11.447,6.252) AM52(-12.269,6.252) AM54(-13.295,6.252) AM55(-14.248,6.252) AM57(-15.195,6.252) AM58(-16.094,6.252) AM60(-17.363,6.501) AN4(17.363,7.184) AN5(16.413,6.762) AN7(15.575,6.762) AN8(15.011,7.088) AN10(13.657,6.762) AN11(13.093,7.088) AN13(11.738,6.762) AN15(11.174,7.088) AN17(10.092,6.569) AN18(9.466,6.903) AN20(8.513,6.903) AN21(7.561,6.903) AN22(6.608,6.903) AN23(5.786,6.903) AN25(4.81,6.903) AN26(3.858,6.903) AN28(2.905,6.903) AN29(1.953,6.903) AN31(1.054,6.578) AN32(0.49,6.903) AN33(-0.412,6.903) AN35(-1.415,6.903) AN36(-2.266,6.903) AN38(-3.32,6.903) AN39(-4.228,6.578) AN40(-4.817,6.903) AN42(-5.63,6.903) AN43(-6.582,6.903) AN45(-7.56,6.903) AN46(-8.487,6.903) AN48(-9.542,6.903) AN49(-10.443,6.903) AN51(-11.447,6.903) AN52(-12.269,6.903) AN54(-13.295,6.903) AN55(-14.248,6.903) AN57(-15.195,6.903) AN58(-16.094,6.903) AN60(-17.038,7.07) AN61(-17.689,7.07) AP4(17.363,7.857) AP5(16.413,7.413) AP7(15.575,7.413) AP8(15.011,7.738) AP10(13.657,7.413) AP11(13.093,7.738) AP13(11.738,7.413) AP15(11.174,7.738) AP17(10.092,7.219) AP18(9.466,7.553) AP20(8.513,7.553) AP21(7.561,7.553) AP22(6.608,7.553) AP23(5.786,7.553) AP25(4.81,7.553) AP26(3.858,7.553) AP28(2.905,7.553) AP29(1.953,7.553) AP31(1.054,7.228) AP32(0.49,7.553) AP33(-0.412,7.553) AP35(-1.415,7.553) AP36(-2.266,7.553) AP38(-3.32,7.553) AP39(-4.228,7.228) AP40(-4.817,7.553) AP42(-5.63,7.553) AP43(-6.582,7.553) AP45(-7.56,7.553) AP46(-8.487,7.553) AP48(-9.542,7.553) AP49(-10.443,7.553) AP51(-11.447,7.553) AP52(-12.269,7.553) AP54(-13.295,7.553) AP55(-14.248,7.553) AP57(-15.195,7.553) AP58(-16.094,7.553) AP60(-17.363,7.746) AR5(16.413,8.063) AR7(15.575,8.063) AR8(15.011,8.388) AR10(13.657,8.063) AR11(13.093,8.388) AR13(11.738,8.063) AR15(11.174,8.388) AR17(10.092,7.869) AR18(9.466,8.203) AR20(8.513,8.203) AR21(7.561,8.203) AR22(6.608,8.203) AR23(5.786,8.203) AR25(4.81,8.203) AR26(3.858,8.203) AR28(2.905,8.203) AR29(1.953,8.203) AR31(1.054,7.878) AR32(0.49,8.203) AR33(-0.412,8.203) AR35(-1.415,8.203) AR36(-2.266,8.203) AR38(-3.32,8.203) AR39(-4.228,7.878) AR40(-4.817,8.203) AR42(-5.63,8.203) AR43(-6.582,8.203) AR45(-7.56,8.203) AR46(-8.487,8.203) AR48(-9.542,8.203) AR49(-10.443,8.203) AR51(-11.447,8.203) AR52(-12.269,8.203) AR54(-13.295,8.203) AR55(-14.248,8.203) AR57(-15.195,8.203) AR58(-16.094,8.203) AT2(18.664,8.645) AT3(18.014,8.683) AT4(17.363,8.683) AT5(16.413,8.713) AT7(15.575,8.713) AT10(13.657,8.713) AT13(11.738,8.713) AT35(-1.122,8.905) AT37(-2.697,8.905) AT40(-4.272,8.905) AT42(-5.847,8.905) AT43(-7.422,8.905) AT46(-8.996,8.905) AT49(-10.597,8.933) AT61(-17.689,8.32) AT62(-18.498,8.376) AU2(18.659,9.333) AU3(17.999,9.333) AU4(17.338,9.333) AU6(15.977,9.363) AU7(15.151,9.363) AU8(14.478,9.363) AU10(13.653,9.363) AU11(12.98,9.363) AU12(12.154,9.363) AU14(11.481,9.363) AU15(10.656,9.363) AU16(10.092,9.038) AU17(9.454,9.363) AU18(8.778,9.038) AU19(8.21,9.363) AU20(7.563,9.038) AU21(6.917,9.363) AU22(6.348,9.038) AU23(5.672,9.363) AU24(4.996,9.038) AU25(4.321,9.363) AU26(3.645,9.038) AU27(3.076,9.363) AU28(2.43,9.038) AU29(1.783,9.363) AU30(1.214,9.038) AU31(0.539,9.363) AU33(-0.058,9.016) AU34(-0.66,9.363) AU35(-1.585,9.363) AU36(-2.235,9.363) AU37(-3.16,9.363) AU39(-3.81,9.363) AU40(-4.734,9.363) AU41(-5.385,9.363) AU42(-6.309,9.363) AU43(-6.959,9.363) AU44(-7.884,9.363) AU46(-8.534,9.363) AU47(-9.459,9.363) AU49(-10.109,9.363) AU50(-11.086,9.363) AU51(-11.666,9.038) AU52(-12.342,9.363) AU53(-13.017,9.038) AU54(-13.586,9.363) AU55(-14.233,9.038) AU56(-14.879,9.363) AU57(-15.448,9.038) AU58(-16.124,9.363) AU59(-16.688,9.038) AU60(-17.251,9.363) AU61(-17.963,9.087) AU62(-18.664,9.349) AV3(17.993,9.993) AV4(17.338,9.993) AV5(16.65,10.014) AV16(10.092,9.689) AV18(8.778,9.689) AV20(7.563,9.689) AV22(6.348,9.689) AV24(4.996,9.689) AV26(3.645,9.689) AV28(2.43,9.689) AV30(1.214,9.689) AV33(-0.086,9.689) AV51(-11.666,9.689) AV53(-13.017,9.689) AV55(-14.233,9.689) AV57(-15.448,9.689) AV59(-16.688,9.689) AV60(-17.251,10.014) AV61(-17.988,9.737) AW4(17.338,10.654) AW59(-16.688,10.339) AW60(-17.251,10.664) B4(17.393,-10.664) B5(16.176,-10.672) B20(7.461,-10.672) B58(-16.023,-10.339) B59(-16.586,-10.664) B60(-17.351,-10.654) C3(18.012,-10.012) C4(17.196,-10.042) C5(16.542,-10.118) C6(15.538,-10.118) C20(7.804,-10.118) C21(7.423,-9.529) C22(6.636,-9.529) C24(5.263,-9.282) C25(4.6,-10.014) C26(4.037,-9.689) C27(3.474,-10.014) C28(2.756,-9.282) C29(2.093,-10.014) C30(1.53,-9.689) C31(0.966,-10.014) C32(0.248,-9.282) C33(-0.415,-10.014) C34(-0.978,-9.689) C35(-1.541,-10.014) C36(-2.259,-9.282) C37(-2.922,-10.014) C38(-3.485,-9.689) C39(-4.049,-10.014) C40(-4.767,-9.282) C41(-5.43,-10.014) C42(-5.993,-9.689) C43(-6.556,-10.014) C44(-7.274,-9.282) C45(-7.937,-10.014) C46(-8.5,-9.689) C47(-9.064,-10.014) C48(-9.756,-9.282) C49(-10.444,-10.014) C50(-11.008,-9.689) C51(-11.571,-10.014) C52(-12.264,-9.323) C53(-12.952,-10.014) C54(-13.515,-9.689) C55(-14.079,-10.014) C56(-14.771,-9.323) C57(-15.459,-10.014) C58(-16.023,-9.689) C59(-16.586,-10.014) C61(-17.689,-10.077) D2(18.664,-9.24) D3(18.014,-9.278) D5(16.636,-9.472) D6(15.945,-9.529) D8(15.157,-9.529) D9(14.37,-9.529) D11(13.462,-9.529) D12(12.579,-9.529) D14(11.792,-9.529) D15(10.884,-9.529) D17(10.001,-9.529) D18(9.214,-9.529) D20(8.306,-9.529) D21(7.079,-8.891) D23(5.937,-9.529) D25(4.6,-9.363) D26(4.037,-9.038) D27(3.474,-9.363) D29(2.093,-9.363) D30(1.53,-9.038) D31(0.966,-9.363) D33(-0.415,-9.363) D34(-0.978,-9.038) D35(-1.541,-9.363) D37(-2.922,-9.363) D38(-3.485,-9.038) D39(-4.049,-9.363) D41(-5.43,-9.363) D42(-5.993,-9.038) D43(-6.556,-9.363) D45(-7.937,-9.363) D46(-8.5,-9.038) D47(-9.064,-9.363) D49(-10.444,-9.363) D50(-11.008,-9.038) D51(-11.571,-9.363) D53(-12.952,-9.363) D54(-13.515,-9.038) D55(-14.079,-9.363) D57(-15.459,-9.363) D58(-16.023,-9.038) D59(-16.586,-9.363) D60(-17.363,-9.513) D61(-18.014,-9.513) D62(-18.664,-9.28) E2(18.664,-8.589) E3(18.014,-8.627) E4(17.363,-8.627) E5(16.712,-8.695) E6(15.76,-8.695) E8(14.807,-8.695) E10(13.855,-8.695) E11(12.902,-8.695) E13(11.95,-8.695) E15(10.997,-8.695) E17(10.045,-8.695) E18(9.092,-8.695) E20(8.14,-8.695) E59(-16.713,-8.667) E60(-17.363,-8.667) E61(-18.014,-8.667) E62(-18.664,-8.629) F2(18.664,-7.84) F3(18.014,-7.802) F4(17.363,-7.802) F5(16.712,-8.045) F6(15.76,-8.045) F8(14.807,-8.045) F10(13.855,-8.045) F11(12.902,-8.045) F13(11.95,-8.045) F15(10.997,-8.045) F17(10.045,-8.045) F18(9.092,-8.045) F20(8.14,-8.045) F59(-16.713,-7.842) F60(-17.363,-7.842) G4(17.363,-7.129) G5(16.712,-7.395) G6(15.76,-7.395) G8(14.807,-7.395) G10(13.855,-7.395) G11(12.902,-7.395) G13(11.95,-7.395) G15(10.997,-7.395) G17(10.045,-7.395) G18(9.092,-7.395) G20(8.14,-7.395) H5(16.712,-6.745) H6(15.76,-6.745) H8(14.807,-6.745) H10(13.855,-6.745) H11(12.902,-6.745) H13(11.95,-6.745) H15(10.997,-6.745) H17(10.045,-6.745) H18(9.092,-6.745) H20(8.14,-6.745) H59(-16.713,-7.169) H60(-17.363,-7.169) J4(17.363,-6.303) J5(16.687,-6.094) J6(15.747,-6.094) J8(14.807,-6.094) J10(13.855,-6.094) J11(12.902,-6.094) J13(11.95,-6.094) J15(10.997,-6.094) J17(10.045,-6.094) J18(9.092,-6.094) J20(8.14,-6.094) J21(7.219,-6.328) J59(-16.713,-6.343) J60(-17.363,-6.343) K4(17.363,-5.63) K59(-16.713,-5.67) K60(-17.363,-5.67) L4(17.363,-4.805) L5(16.678,-4.977) L6(16.027,-4.977) L7(15.377,-4.977) L8(14.727,-4.977) L59(-16.713,-4.845) L60(-17.363,-4.845) N4(17.363,-4.132) N5(16.678,-4.024) N6(16.027,-4.024) N7(15.377,-4.024) N8(14.727,-4.024) N59(-16.713,-4.172) N60(-17.363,-4.172) P4(17.363,-3.306) P59(-16.713,-3.346) P60(-17.363,-3.346) R5(16.678,-3.072) R6(16.027,-3.072) R7(15.377,-3.072) R8(14.727,-3.072) T4(17.363,-2.633) T59(-16.713,-2.673) T60(-17.363,-2.673) U4(17.363,-1.807) U5(16.678,-2.119) U6(16.027,-2.119) U7(15.377,-2.119) U8(14.727,-2.119) U59(-16.713,-1.848) U60(-17.363,-1.848) V4(17.363,-1.134) V5(16.678,-1.167) V6(16.027,-1.167) V7(15.377,-1.167) V8(14.727,-1.167) V59(-16.713,-1.174) V60(-17.363,-1.174) Y4(17.363,-0.309) Y5(16.678,-0.214) Y6(16.027,-0.214) Y7(15.377,-0.214) Y8(14.727,-0.214) Y59(-16.713,-0.349) Y60(-17.363,-0.349)
  round 0.381 smd: AA9(14.282,0.262) AA21(7.627,0.175) AA23(6.199,0.175) AA58(-16.063,0.015) AB10(13.838,0.738) AB20(8.135,0.582) AB21(7.627,0.988) AB22(6.707,0.582) AB23(6.199,0.988) AB57(-15.743,0.666) AC9(14.282,1.215) AC20(8.135,1.394) AC22(6.707,1.394) AC58(-16.063,1.316) AD10(13.838,1.691) AD21(7.627,1.801) AD23(6.199,1.801) AD57(-15.743,1.966) AE9(14.282,2.167) AE10(13.838,2.643) AE20(8.135,2.207) AE21(7.627,2.614) AE22(6.707,2.207) AE23(6.199,2.614) AE58(-16.063,2.616) AF9(14.282,3.12) AF11(13.255,2.968) AF12(12.442,2.968) AF14(11.63,2.968) AF15(10.817,2.968) AF17(10.004,2.968) AF18(9.191,2.968) AF20(8.378,2.968) AF22(6.707,3.02) AG10(13.662,3.476) AG11(12.849,3.476) AG13(12.036,3.476) AG14(11.223,3.476) AG16(10.41,3.476) AG17(9.598,3.476) AG19(8.785,3.476) AG20(7.972,3.476) AG23(6.199,3.426) AG57(-15.743,3.267) AG58(-16.377,3.695) AH22(6.707,3.833) AH24(5.394,3.975) AH26(4.094,3.975) AH28(2.793,3.975) AH30(1.493,3.975) AH32(0.192,3.975) AH34(-1.108,3.975) AH36(-2.409,3.975) AH38(-3.709,3.975) AH40(-5.01,3.975) AH42(-6.31,3.975) AH44(-7.611,3.975) AH46(-8.911,3.975) AH49(-10.212,3.975) AH51(-11.512,3.975) AH53(-12.813,3.975) AH55(-14.113,3.975) AH57(-15.413,3.975) AJ23(6.199,4.239) AJ25(4.744,4.3) AJ27(3.443,4.3) AJ29(2.143,4.3) AJ31(0.843,4.3) AJ33(-0.458,4.3) AJ35(-1.758,4.3) AJ37(-3.059,4.3) AJ39(-4.359,4.3) AJ41(-5.66,4.3) AJ43(-6.96,4.3) AJ45(-8.261,4.3) AJ47(-9.561,4.3) AJ50(-10.862,4.3) AJ52(-12.162,4.3) AJ54(-13.463,4.3) AJ56(-14.763,4.3) AJ58(-16.064,4.3) AW2(18.654,10.654) AW61(-18.014,10.664) AW62(-18.664,10.664) B3(18.056,-10.664) B62(-18.664,-10.59) C2(18.664,-10.056) E23(5.981,-8.713) E25(4.6,-8.713) E27(3.474,-8.713) E29(2.093,-8.713) E31(0.966,-8.713) E33(-0.415,-8.713) E35(-1.541,-8.713) E37(-2.922,-8.713) E39(-4.049,-8.713) E41(-5.43,-8.713) E43(-6.556,-8.713) E45(-7.937,-8.713) E47(-9.064,-8.713) E49(-10.444,-8.713) E51(-11.571,-8.713) E53(-12.952,-8.713) E55(-14.079,-8.713) E57(-15.459,-8.713) F22(6.597,-8.256) F24(5.291,-8.188) F26(4.037,-8.188) F28(2.783,-8.188) F30(1.53,-8.188) F32(0.276,-8.188) F34(-0.978,-8.188) F36(-2.232,-8.188) F38(-3.485,-8.188) F40(-4.739,-8.188) F42(-5.993,-8.188) F44(-7.247,-8.188) F46(-8.5,-8.188) F48(-9.754,-8.188) F50(-11.008,-8.188) F52(-12.262,-8.188) F54(-13.515,-8.188) F56(-14.769,-8.188) F58(-16.063,-8.188) G22(6.707,-7.546) G23(5.981,-7.863) G25(4.6,-7.863) G27(3.474,-7.863) G29(2.093,-7.863) G31(0.966,-7.863) G33(-0.415,-7.863) G35(-1.541,-7.863) G37(-2.922,-7.863) G39(-4.049,-7.863) G41(-5.43,-7.863) G43(-6.556,-7.863) G45(-7.937,-7.863) G47(-9.064,-7.863) G49(-10.444,-7.863) G51(-11.571,-7.863) G53(-12.952,-7.863) G55(-14.079,-7.863) G57(-15.459,-7.863) H22(6.707,-6.734) H23(6.199,-7.14) H57(-15.743,-7.213) J22(6.707,-5.921) J23(6.199,-6.327) J58(-16.063,-6.487) K9(14.282,-5.453) K10(13.379,-5.614) K12(12.426,-5.614) K14(11.474,-5.614) K16(10.521,-5.614) K18(9.569,-5.614) K19(8.616,-5.614) K21(7.664,-5.614) K23(6.199,-5.514) K57(-15.743,-5.837) L10(13.838,-4.977) L11(12.902,-5.17) L13(11.95,-5.17) L15(10.997,-5.17) L17(10.045,-5.17) L18(9.092,-5.17) L20(8.135,-5.108) L22(6.707,-5.108) L58(-16.063,-5.186) M9(14.282,-4.5) M20(8.135,-4.295) M21(7.627,-4.702) M22(6.707,-4.295) M23(6.199,-4.702) M57(-15.743,-4.536) N10(13.838,-4.024) N21(7.627,-3.889) N23(6.199,-3.889) N58(-16.063,-3.886) P9(14.282,-3.548) P20(8.135,-3.482) P22(6.707,-3.482) P57(-15.743,-3.236) R10(13.838,-3.072) R20(8.135,-2.67) R21(7.627,-3.076) R22(6.707,-2.67) R23(6.199,-3.076) T9(14.282,-2.595) T21(7.627,-2.263) T23(6.199,-2.263) T58(-16.063,-2.585) U9(14.282,-1.643) U10(13.838,-2.119) U20(8.135,-1.857) U22(6.707,-1.857) U57(-15.743,-1.935) V10(13.838,-1.167) V21(7.627,-1.45) V23(6.199,-1.45) V58(-16.063,-1.285) W9(14.282,-0.69) W20(8.135,-1.044) W21(7.627,-0.638) W22(6.707,-1.044) W23(6.199,-0.638) W57(-15.743,-0.635) Y10(13.838,-0.214) Y20(8.135,-0.231) Y22(6.707,-0.231)
  round 0.33 smd: AK22(6.659,4.952) AK23(5.786,4.952) AK25(4.81,4.952) AK26(3.858,4.952) AK28(2.905,4.952) AK29(2.004,4.952) AK32(0.49,4.952) AK33(-0.412,4.952) AK35(-1.415,4.952) AK36(-2.266,4.952) AK38(-3.295,4.952) AK40(-4.792,4.952) AK42(-5.63,4.952) AK43(-6.582,4.952) AK45(-7.56,4.952) AK46(-8.462,4.952) AK48(-9.516,4.952) AK49(-10.418,4.952) AK51(-11.421,4.952) AK52(-12.269,4.952) AK54(-13.295,4.952) AK55(-14.248,4.952) AK57(-15.195,4.952) AK58(-16.094,4.952)
C144KA-108A7-L-1
  round 1.422 hole 1.016: 1(7,0) 2(5,0) 3(3,0) 4(1,0) 5(-1,0) 6(-3,0) 7(-5,0) 8(-7,0)
  oval 1.422x3.404 hole 0.711x2.692: 9(10.125,0) 10(-10.125,0)
C402H20
  custom 0.14x0.14 smd: 1(0,0.445) 2(0,-0.445)
C402H22
  custom 0.14x0.14 smd: 1(0,0.445) 2(0,-0.445)
C402H24
  custom 0.14x0.14 smd: 1(0,0.445) 2(0,-0.445)
C603
  custom 0.197x0.197 smd: 1(0,0.66) 2(0,-0.66)
C603H36
  custom 0.197x0.197 smd: 1(0,0.66) 2(0,-0.66)
C603H38
  custom 0.197x0.197 smd: 1(0,0.66) 2(0,-0.66)
C603H40
  custom 0.197x0.197 smd: 1(0,0.66) 2(0,-0.66)
C805H54
  rect 1.549x0.94 smd: 1(0,0.838) 2(0,-0.838)
C805H56
  rect 1.549x0.94 smd: 1(0,0.838) 2(0,-0.838)
C805H58
  rect 1.549x0.94 smd: 1(0,0.838) 2(0,-0.838)
C1206H71
  rect 1.854x1.27 smd: 1(0,1.397) 2(0,-1.397)
CON2O-U
  custom 0.159x0.159 smd: 1(0,0.254) 2(0,-0.254)
CT3528H79
  rect 2.286x2.286 smd: 1(0,1.905) 2(0,-1.905)
CT7343H79
  rect 2.413x2.286 smd: 1(0,3.15) 2(0,-3.15)
CT7343H119
  rect 2.413x2.286 smd: 1(0,3.15) 2(0,-3.15)
D5436AKH98
  rect 2.286x2.032 smd: A(0,2.438) K(0,-2.438)
DFN8J4535-G4122-U1H40
  rect 0.203x0.94 smd: 1(1.6,1.788) 2(1.2,1.788) 3(0.8,1.788) 6(0.8,-1.788) 7(1.2,-1.788) 8(1.6,-1.788)
  rect 2.21x0.94 smd: 4(-0.6,1.788) 5(-0.6,-1.788)
  rect 4.039x2.21 smd: 9(0,0)
DFN9J2015H32
  rect 0.203x0.787 smd: 1(0.6,0.737) 2(0.2,0.737) 7(0.2,-0.737) 8(0.6,-0.737)
  rect 0.61x1.016 smd: 3(-0.4,0.623) 6(-0.4,-0.623)
  rect 0.025x0.025 smd: 4(-0.6,0.737) 5(-0.6,-0.737)
  rect 1.041x0.203 smd: 9(0.86,0)
DFN10G2510H26
  rect 0.305x0.787 smd: 1(1,0.494) 5(-1,0.494) 6(-1,-0.494) 10(1,-0.494)
  rect 0.254x0.787 smd: 2(0.521,0.494) 4(-0.521,0.494) 7(-0.521,-0.494) 9(0.521,-0.494)
  rect 0.025x0.025 smd: 3(0,0.494)
  rect 0.406x1.753 smd: 8(0,-0.494)
DS2RK-20401-TP4B-U
  round 0.254 hole 1.118 unplated: (-33.4,0)
  round 0.254 hole 1.6 unplated: (33.4,0)
  custom 0.114x0.114 smd: 1(31.65,4.1) 2(31.35,-4.1) 3(31.05,4.1) 4(30.751,-4.1) 5(30.45,4.1) 6(30.15,-4.1) 7(29.85,4.1) 8(29.55,-4.1) 9(29.251,4.1) 10(28.95,-4.1) 11(28.65,4.1) 12(28.35,-4.1) 13(28.051,4.1) 14(27.751,-4.1) 15(27.45,4.1) 16(27.15,-4.1) 17(26.851,4.1) 18(26.551,-4.1) 19(26.25,4.1) 20(25.95,-4.1) 21(25.65,4.1) 22(25.35,-4.1) 23(25.051,4.1) 24(24.75,-4.1) 25(24.45,4.1) 26(24.15,-4.1) 27(23.851,4.1) 28(23.55,-4.1) 29(23.25,4.1) 30(22.95,-4.1) 31(22.651,4.1) 32(22.351,-4.1) 33(22.05,4.1) 34(21.75,-4.1) 35(21.451,4.1) 36(21.151,-4.1) 37(20.85,4.1) 38(20.55,-4.1) 39(20.25,4.1) 40(19.95,-4.1) 41(19.65,4.1) 42(19.35,-4.1) 43(19.049,4.1) 44(18.749,-4.1) 45(18.45,4.1) 46(18.15,-4.1) 47(17.85,4.1) 48(17.549,-4.1) 49(17.25,4.1) 50(16.95,-4.1) 51(16.65,4.1) 52(16.349,-4.1) 53(16.049,4.1) 54(15.75,-4.1) 55(15.45,4.1) 56(15.15,-4.1) 57(14.849,4.1) 58(14.549,-4.1) 59(14.25,4.1) 60(13.95,-4.1) 61(13.649,4.1) 62(13.349,-4.1) 63(13.05,4.1) 64(12.75,-4.1) 65(12.45,4.1) 66(12.149,-4.1) 67(11.85,4.1) 68(11.55,-4.1) 69(11.25,4.1) 70(10.95,-4.1) 71(10.649,4.1) 72(10.349,-4.1) 73(7.65,4.1) 74(7.35,-4.1) 75(7.049,4.1) 76(6.749,-4.1) 77(6.45,4.1) 78(6.15,-4.1) 79(5.85,4.1) 80(5.549,-4.1) 81(5.25,4.1) 82(4.95,-4.1) 83(4.65,4.1) 84(4.349,-4.1) 85(4.05,4.1) 86(3.75,-4.1) 87(3.45,4.1) 88(3.15,-4.1) 89(2.849,4.1) 90(2.549,-4.1) 91(2.25,4.1) 92(1.95,-4.1) 93(1.649,4.1) 94(1.349,-4.1) 95(1.05,4.1) 96(0.75,-4.1) 97(0.45,4.1) 98(0.149,-4.1) 99(-0.15,4.1) 100(-0.45,-4.1) 101(-0.75,4.1) 102(-1.051,-4.1) 103(-1.351,4.1) 104(-1.65,-4.1) 105(-1.95,4.1) 106(-2.25,-4.1) 107(-2.551,4.1) 108(-2.851,-4.1) 109(-3.15,4.1) 110(-3.45,-4.1) 111(-3.751,4.1) 112(-4.051,-4.1) 113(-4.35,4.1) 114(-4.65,-4.1) 115(-4.95,4.1) 116(-5.251,-4.1) 117(-5.55,4.1) 118(-5.85,-4.1) 119(-6.15,4.1) 120(-6.451,-4.1) 121(-6.751,4.1) 122(-7.051,-4.1) 123(-7.35,4.1) 124(-7.65,-4.1) 125(-7.951,4.1) 126(-8.251,-4.1) 127(-8.55,4.1) 128(-8.85,-4.1) 129(-9.15,4.1) 130(-9.451,-4.1) 131(-9.75,4.1) 132(-10.05,-4.1) 133(-10.35,4.1) 134(-10.651,-4.1) 135(-10.95,4.1) 136(-11.25,-4.1) 137(-11.55,4.1) 138(-11.85,-4.1) 139(-12.151,4.1) 140(-12.451,-4.1) 141(-12.75,4.1) 142(-13.05,-4.1) 143(-13.351,4.1) 144(-13.651,-4.1) 145(-13.95,4.1) 146(-14.25,-4.1) 147(-14.55,4.1) 148(-14.851,-4.1) 149(-15.15,4.1) 150(-15.45,-4.1) 151(-15.75,4.1) 152(-16.051,-4.1) 153(-16.35,4.1) 154(-16.65,-4.1) 155(-16.95,4.1) 156(-17.25,-4.1) 157(-17.551,4.1) 158(-17.851,-4.1) 159(-18.15,4.1) 160(-18.45,-4.1) 161(-18.751,4.1) 162(-19.051,-4.1) 163(-19.35,4.1) 164(-19.65,-4.1) 165(-19.95,4.1) 166(-20.251,-4.1) 167(-20.55,4.1) 168(-20.85,-4.1) 169(-21.15,4.1) 170(-21.451,-4.1) 171(-21.751,4.1) 172(-22.051,-4.1) 173(-22.35,4.1) 174(-22.65,-4.1) 175(-22.951,4.1) 176(-23.251,-4.1) 177(-23.55,4.1) 178(-23.85,-4.1) 179(-24.151,4.1) 180(-24.451,-4.1) 181(-24.75,4.1) 182(-25.05,-4.1) 183(-25.35,4.1) 184(-25.651,-4.1) 185(-25.95,4.1) 186(-26.25,-4.1) 187(-26.55,4.1) 188(-26.851,-4.1) 189(-27.151,4.1) 190(-27.451,-4.1) 191(-27.75,4.1) 192(-28.05,-4.1) 193(-28.351,4.1) 194(-28.651,-4.1) 195(-28.95,4.1) 196(-29.25,-4.1) 197(-29.55,4.1) 198(-29.851,-4.1) 199(-30.15,4.1) 200(-30.45,-4.1) 201(-30.75,4.1) 202(-31.05,-4.1) 203(-31.349,4.1) 204(-31.649,-4.1)
  rect 3.505x4.597 smd: 205(32.8,12) 206(-32.8,12)
GAP-CLOSE-PWR
  rect 0.66x0.762 smd: 1(-0.305,0) 2(0.305,0)
GAP-CLOSE-PWR-3
  rect 0.66x0.762 smd: 1(-0.305,0) 2(0.305,0)
GS12201-1011-9H
  round 0.254 hole 0.965 unplated: (-5.8,0) (5.8,0)
  rect 0.305x1.143 smd: 1(4.75,-2.325) 2(4.25,-2.325) 3(3.75,-2.325) 4(3.25,-2.325) 5(2.75,-2.325) 6(2.25,-2.325) 7(1.75,-2.325) 8(1.25,-2.325) 9(0.75,-2.325) 10(0.25,-2.325) 11(-0.25,-2.325) 12(-0.75,-2.325) 13(-1.25,-2.325) 14(-1.75,-2.325) 15(-2.25,-2.325) 16(-2.75,-2.325) 17(-3.25,-2.325) 18(-3.75,-2.325) 19(-4.25,-2.325) 20(-4.75,-2.325)
  rect 1.295x1.397 smd: 21(5.8,1.8) 22(5.8,-2.2) 23(-5.8,1.8) 24(-5.8,-2.2)
HOLE335R178
  round 8.509 hole 4.521: 1(0,0)
HOLE335R229
  round 8.509 hole 5.817: 1(0,0)
L603H40
  custom 0.197x0.197 smd: 1(0,0.66) 2(0,-0.66)
L4947-1015H119
  rect 1.753x1.88 smd: 1(0,2.045) 2(0,-2.045)
L7066-1830-UH119
  rect 3.505x2.921 smd: 1(0,2.78) 2(0,-2.78)
L109100-2430-UH158
  rect 3.505x3.556 smd: 1(0,4.397) 2(0,-4.397)
L125100-4PH24
  rect 0.457x0.838 smd: 1(-0.326,-0.587) 2(0.326,-0.587) 3(0.326,0.587) 4(-0.326,0.587)
L736630H119
  rect 3.251x2.743 smd: 1(0,2.819) 2(0,-2.819)
L11510030H158
  rect 3.251x3.454 smd: 1(0,4.928) 2(0,-4.928)
LGA9G2310H13
  rect 0.305x0.381 smd: 1(1,0.31) 5(-1,0.31) 6(-1,-0.31) 9(1,-0.31)
  rect 0.254x0.381 smd: 2(0.526,0.31) 4(-0.526,0.31) 7(-0.526,-0.31) 8(0.526,-0.31)
  rect 0.406x0.991 smd: 3(0,0)
LGA16-3030-H40
  rect 0.305x0.559 smd: 1(1,1.221) 2(0.5,1.221) 3(0,1.221) 4(-0.5,1.221) 5(-1,1.221) 9(-1,-1.221) 10(-0.5,-1.221) 11(0,-1.221) 12(0.5,-1.221) 13(1,-1.221)
  rect 0.559x0.305 smd: 6(-1.221,0.5) 7(-1.221,0) 8(-1.221,-0.5) 14(1.221,-0.5) 15(1.221,0) 16(1.221,0.5)
LQFP128H63
  rect 0.203x1.524 smd: 1(6.2,7.747) 2(5.8,7.747) 3(5.4,7.747) 4(5,7.747) 5(4.6,7.747) 6(4.2,7.747) 7(3.8,7.747) 8(3.4,7.747) 9(3,7.747) 10(2.6,7.747) 11(2.2,7.747) 12(1.8,7.747) 13(1.4,7.747) 14(0.999,7.747) 15(0.599,7.747) 16(0.199,7.747) 17(-0.199,7.747) 18(-0.599,7.747) 19(-0.999,7.747) 20(-1.4,7.747) 21(-1.8,7.747) 22(-2.2,7.747) 23(-2.6,7.747) 24(-3,7.747) 25(-3.4,7.747) 26(-3.8,7.747) 27(-4.2,7.747) 28(-4.6,7.747) 29(-5,7.747) 30(-5.4,7.747) 31(-5.8,7.747) 32(-6.2,7.747) 65(-6.2,-7.747) 66(-5.8,-7.747) 67(-5.4,-7.747) 68(-5,-7.747) 69(-4.6,-7.747) 70(-4.2,-7.747) 71(-3.8,-7.747) 72(-3.4,-7.747) 73(-3,-7.747) 74(-2.6,-7.747) 75(-2.2,-7.747) 76(-1.8,-7.747) 77(-1.4,-7.747) 78(-0.999,-7.747) 79(-0.599,-7.747) 80(-0.199,-7.747) 81(0.199,-7.747) 82(0.599,-7.747) 83(0.999,-7.747) 84(1.4,-7.747) 85(1.8,-7.747) 86(2.2,-7.747) 87(2.6,-7.747) 88(3,-7.747) 89(3.4,-7.747) 90(3.8,-7.747) 91(4.2,-7.747) 92(4.6,-7.747) 93(5,-7.747) 94(5.4,-7.747) 95(5.8,-7.747) 96(6.2,-7.747)
  rect 1.524x0.203 smd: 33(-7.747,6.2) 34(-7.747,5.8) 35(-7.747,5.4) 36(-7.747,5) 37(-7.747,4.6) 38(-7.747,4.2) 39(-7.747,3.8) 40(-7.747,3.4) 41(-7.747,3) 42(-7.747,2.6) 43(-7.747,2.2) 44(-7.747,1.8) 45(-7.747,1.4) 46(-7.747,0.999) 47(-7.747,0.599) 48(-7.747,0.199) 49(-7.747,-0.199) 50(-7.747,-0.599) 51(-7.747,-0.999) 52(-7.747,-1.4) 53(-7.747,-1.8) 54(-7.747,-2.2) 55(-7.747,-2.6) 56(-7.747,-3) 57(-7.747,-3.4) 58(-7.747,-3.8) 59(-7.747,-4.2) 60(-7.747,-4.6) 61(-7.747,-5) 62(-7.747,-5.4) 63(-7.747,-5.8) 64(-7.747,-6.2) 97(7.747,-6.2) 98(7.747,-5.8) 99(7.747,-5.4) 100(7.747,-5) 101(7.747,-4.6) 102(7.747,-4.2) 103(7.747,-3.8) 104(7.747,-3.4) 105(7.747,-3) 106(7.747,-2.6) 107(7.747,-2.2) 108(7.747,-1.8) 109(7.747,-1.4) 110(7.747,-0.999) 111(7.747,-0.599) 112(7.747,-0.199) 113(7.747,0.199) 114(7.747,0.599) 115(7.747,0.999) 116(7.747,1.4) 117(7.747,1.8) 118(7.747,2.2) 119(7.747,2.6) 120(7.747,3) 121(7.747,3.4) 122(7.747,3.8) 123(7.747,4.2) 124(7.747,4.6) 125(7.747,5) 126(7.747,5.4) 127(7.747,5.8) 128(7.747,6.2)
LVD-A40SFYG
  rect 0.305x1.295 smd: 1(-9.75,-1.95) 2(-9.25,-1.95) 3(-8.75,-1.95) 4(-8.25,-1.95) 5(-7.75,-1.95) 6(-7.25,-1.95) 7(-6.75,-1.95) 8(-6.25,-1.95) 9(-5.75,-1.95) 10(-5.25,-1.95) 11(-4.75,-1.95) 12(-4.25,-1.95) 13(-3.75,-1.95) 14(-3.25,-1.95) 15(-2.75,-1.95) 16(-2.25,-1.95) 17(-1.75,-1.95) 18(-1.25,-1.95) 19(-0.75,-1.95) 20(-0.25,-1.95) 21(0.25,-1.95) 22(0.75,-1.95) 23(1.25,-1.95) 24(1.75,-1.95) 25(2.25,-1.95) 26(2.75,-1.95) 27(3.25,-1.95) 28(3.75,-1.95) 29(4.25,-1.95) 30(4.75,-1.95) 31(5.25,-1.95) 32(5.75,-1.95) 33(6.25,-1.95) 34(6.75,-1.95) 35(7.25,-1.95) 36(7.75,-1.95) 37(8.25,-1.95) 38(8.75,-1.95) 39(9.25,-1.95) 40(9.75,-1.95)
  rect 1.194x3.2 smd: 41(-12.15,0) 45(12.15,0)
  rect 2.311x1.295 smd: 42(-8.9,1.95) 43(0,1.95) 44(8.9,1.95)
MSOP8-1H44
  rect 0.356x1.524 smd: 1(-0.975,-2.055) 2(-0.325,-2.055) 3(0.325,-2.055) 4(0.975,-2.055) 5(0.975,2.055) 6(0.325,2.055) 7(-0.325,2.055) 8(-0.975,2.055)
MSOP10-G2D5H44
  rect 0.305x1.372 smd: 1(-1,-2.146) 2(-0.5,-2.146) 3(0,-2.146) 4(0.5,-2.146) 5(1,-2.146) 6(1,2.146) 7(0.5,2.146) 8(0,2.146) 9(-0.5,2.146) 10(-1,2.146)
  rect 2.489x2.489 smd: 11(0,0)
NSS507-212F-BAAG1W-A
  round 0.254 hole 0.965 unplated: (-1.5,0) (1.5,0)
  rect 0.711x1.092 smd: 1(-2.25,2.049) 2(0.751,2.049) 3(2.25,2.049)
  rect 0.991x0.813 smd: 4(-3.745,1.156) 5(-3.745,-1.156) 6(3.745,1.156) 7(3.745,-1.156)
NTC-402H22-U
  custom 0.14x0.14 smd: 1(0,0.445) 2(0,-0.445)
NTC-603H38
  custom 0.216x0.216 smd: 1(0,0.762) 2(0,-0.762)
OSC-3225-4P-3H36
  rect 1.397x0.914 smd: 1(-1.171,-0.825) 2(1.171,-0.825) 3(1.171,0.825) 4(-1.171,0.825)
OSC-3225-4P-4H36
  rect 1.397x1.067 smd: 1(-1.171,-0.756) 2(1.171,-0.756) 3(1.171,0.756) 4(-1.171,0.756)
POLYSW-2114H30
  rect 1.6x0.965 smd: 1(0,0.94) 2(0,-0.94)
POLYSW-2114H50
  rect 1.6x0.965 smd: 1(0,0.94) 2(0,-0.94)
POLYSW-4633-UH43
  rect 3.505x1.626 smd: 1(0,1.834) 2(0,-1.834)
PPAK-8P-2H45
  rect 0.406x1.168 smd: 1(-0.975,-2.351) 2(-0.325,-2.351) 3(0.325,-2.351) 4(0.975,-2.351)
  rect 3.404x2.769 smd: 5(0,0)
  rect 0.025x0.025 smd: 6(1.029,0.902) 7(0.013,0.902) 8(-0.991,0.902)
PPAK-8P-G5324H44-COLAY
  rect 0.762x1.016 smd: 1(-1.905,-3.01) 2(-0.635,-3.01) 3(0.635,-3.01) 4(1.905,-3.01) 5(1.905,3.01) 6(0.635,3.01) 7(-0.635,3.01) 8(-1.905,3.01)
  rect 5.207x2.896 smd: 9(0,0.65)
  rect 5.207x0.787 smd: 10(0,-1.7)
QFN10M3-G4P-UH34
  rect 0.61x0.254 smd: 1(1.346,1.125) 2(1.346,0.675) 3(1.346,0.225) 4(1.346,-0.225) 5(1.346,-0.675) 6(1.346,-1.125)
  rect 0.254x1.168 smd: 7(0.66,-1.067)
  rect 1.981x0.914 smd: 8(-0.66,-0.94)
  custom 0.483x0.483 smd: 9(-0.432,0.051)
  rect 1.143x0.813 smd: 10(-0.241,0.991)
QFN16-G1D8-UH32
  rect 0.305x0.914 smd: 1(0.75,1.551) 2(0.25,1.551) 3(-0.25,1.551) 4(-0.75,1.551) 9(-0.75,-1.551) 10(-0.25,-1.551) 11(0.25,-1.551) 12(0.75,-1.551)
  rect 0.914x0.305 smd: 5(-1.551,0.75) 6(-1.551,0.25) 7(-1.551,-0.25) 8(-1.551,-0.75) 13(1.551,-0.75) 14(1.551,-0.25) 15(1.551,0.25) 16(1.551,0.75)
  rect 1.778x1.778 smd: 17(0,0)
QFN20-G1D75H32
  rect 0.203x0.914 smd: 1(0.8,1.551) 2(0.4,1.551) 3(0,1.551) 4(-0.4,1.551) 5(-0.8,1.551) 11(-0.8,-1.551) 12(-0.4,-1.551) 13(0,-1.551) 14(0.4,-1.551) 15(0.8,-1.551)
  rect 0.914x0.203 smd: 6(-1.551,0.8) 7(-1.551,0.4) 8(-1.551,0) 9(-1.551,-0.4) 10(-1.551,-0.8) 16(1.551,-0.8) 17(1.551,-0.4) 18(1.551,0) 19(1.551,0.4) 20(1.551,0.8)
  rect 1.753x1.753 smd: 21(0,0)
QFN28-G2D7H32
  rect 0.203x0.94 smd: 1(1.2,2.032) 2(0.8,2.032) 3(0.4,2.032) 4(0,2.032) 5(-0.4,2.032) 6(-0.8,2.032) 7(-1.2,2.032) 15(-1.2,-2.032) 16(-0.8,-2.032) 17(-0.4,-2.032) 18(0,-2.032) 19(0.4,-2.032) 20(0.8,-2.032) 21(1.2,-2.032)
  rect 0.94x0.203 smd: 8(-2.032,1.2) 9(-2.032,0.8) 10(-2.032,0.4) 11(-2.032,0) 12(-2.032,-0.4) 13(-2.032,-0.8) 14(-2.032,-1.2) 22(2.032,-1.2) 23(2.032,-0.8) 24(2.032,-0.4) 25(2.032,0) 26(2.032,0.4) 27(2.032,0.8) 28(2.032,1.2)
  rect 2.692x2.692 smd: 29(0,0)
QFN32J4-G2D9-U1H40
  rect 0.203x0.864 smd: 1(1.4,2.085) 2(1,2.085) 3(0.6,2.085) 4(0.2,2.085) 5(-0.2,2.085) 6(-0.6,2.085) 7(-1,2.085) 8(-1.4,2.085) 17(-1.4,-2.085) 18(-1,-2.085) 19(-0.6,-2.085) 20(-0.2,-2.085) 21(0.2,-2.085) 22(0.6,-2.085) 23(1,-2.085) 24(1.4,-2.085)
  rect 0.864x0.203 smd: 9(-2.085,1.4) 10(-2.085,1) 11(-2.085,0.6) 12(-2.085,0.2) 13(-2.085,-0.2) 14(-2.085,-0.6) 15(-2.085,-1) 16(-2.085,-1.4) 25(2.085,-1.4) 26(2.085,-1) 27(2.085,-0.6) 28(2.085,-0.2) 29(2.085,0.2) 30(2.085,0.6) 31(2.085,1) 32(2.085,1.4)
  rect 2.692x2.692 smd: 33(0,0)
